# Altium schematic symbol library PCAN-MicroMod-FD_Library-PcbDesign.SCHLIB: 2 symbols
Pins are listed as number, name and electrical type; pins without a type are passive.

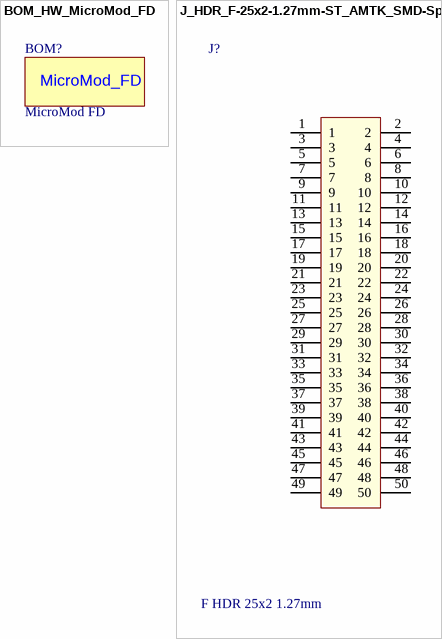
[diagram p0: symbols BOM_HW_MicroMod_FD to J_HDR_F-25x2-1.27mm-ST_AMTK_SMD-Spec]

## BOM_HW_MicroMod_FD
designator BOM?, comment MicroMod FD
Ersteller_Datum: C.Egg_2019-04-01; Hersteller1-Nr.: IPEH-003080; Hersteller1: Peak-System Technik; Prüfer_Datum: MaRe_2019-08-05; Typ: PEAK_BOM
footprint BOM_HW_MicroMod_FD

## J_HDR_F-25x2-1.27mm-ST_AMTK_SMD-Spec
designator J?, comment F HDR 25x2 1.27mm
MicroMod FD Connector; Temp.-max.: +105°C; Temp.-min.: -40°C; Ersteller_Datum: C.Egg_2019_04_01; Gehaeuse: SMD-Spec_34.85x4.6x4.6; Hersteller1-Nr.: 5PS3MSA44-225GONPNRU-00; Hersteller1: Amtek Technology; Lieferer1a: AMEC; Spannung: 500V; Prüfer_Datum: MaRe_2019-07-19; Typ: PEAK_J
footprint J_HDR_F-25x2-1.27mm-ST_AMTK_SMD-Spec
pins: 1, 2, 3, 4, 5, 6, 7, 8, 9, 10, 11, 12, 13, 14, 15, 16, 17, 18, 19, 20, 21, 22, 23, 24, 25, 26, 27, 28, 29, 30, 31, 32, 33, 34, 35, 36, 37, 38, 39, 40, 41, 42, 43, 44, 45, 46, 47, 48, 49, 50
2 alternate drawings of the same symbol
